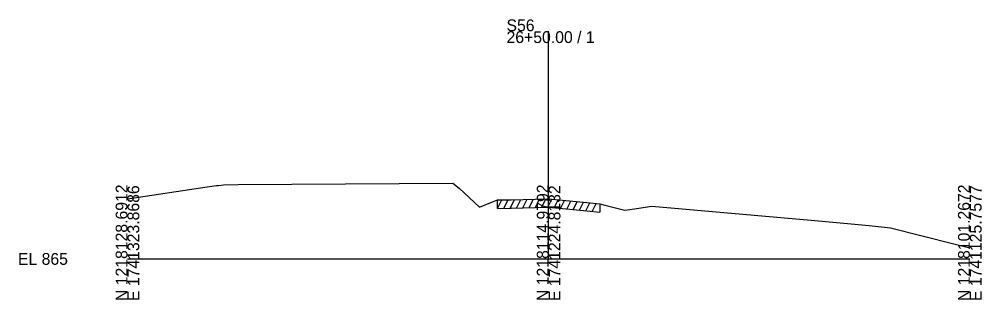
# Model space of a CAD drawing. Extents: x -26 to 1203, y -10 to 19541.
# Drawn here: x -25.7 to 202.8, y 1490.3 to 1556.9 of the extents above; entities that cross this region are included whole.
import ezdxf

# ---------------------------------------------------------------- set-up
doc = ezdxf.new("R2010")
doc.units = 0
for name, color, linetype in [('RD_GPK_XS_Cell', 7, 'Continuous'), ('RD_XS_ExGround', 7, 'Continuous'), ('RD_XS_ExPaveRet', 7, 'Continuous'), ('RD_XS_TX_Elev_EX', 7, 'Continuous')]:
    doc.layers.add(name, color=color, linetype=linetype)

msp = doc.modelspace()

# ---------------------------------------------------------------- linework, layer by layer
at = {"layer": 'RD_GPK_XS_Cell'}
for p, q in [((100, 1500), (100, 1554.08)), ((0, 1500), (100, 1500)), ((100, 1500), (200, 1500))]:
    msp.add_line(p, q, dxfattribs=at)
at = {"layer": 'RD_XS_ExGround'}
msp.add_lwpolyline([(0, 1514.29), (18.94, 1517.09), (21.17, 1517.41), (21.62, 1517.45), (22.84, 1517.63), (26.26, 1517.67), (77.27, 1518.03), (78.79, 1516.77), (83.55, 1512.26), (86.66, 1513.6), (87.85, 1514), (91.08, 1514.05), (99.65, 1514.31), (100, 1514.27), (109.1, 1513.39), (112.14, 1513.09), (113.35, 1512.78), (118.06, 1511.62), (119.86, 1511.84), (124.49, 1512.5), (163.23, 1509.13), (176.07, 1507.97), (181.16, 1507.35), (196.19, 1503.62), (200, 1502.67)], dxfattribs=at)
at = {"layer": 'RD_XS_ExPaveRet'}
for p, q in [((87.85, 1512), (88.86, 1514.01)), ((87.85, 1512), (87.85, 1514)), ((89.35, 1512.02), (90.36, 1514.04)), ((90.85, 1512.04), (91.86, 1514.07)), ((92.35, 1512.08), (93.37, 1514.12)), ((93.85, 1512.13), (94.87, 1514.16)), ((95.35, 1512.18), (96.37, 1514.21)), ((96.85, 1512.22), (97.87, 1514.25)), ((98.35, 1512.27), (99.37, 1514.3)), ((99.85, 1512.29), (100.8, 1514.19)), ((101.35, 1512.14), (102.3, 1514.05)), ((102.85, 1511.99), (103.8, 1513.9)), ((104.35, 1511.85), (105.3, 1513.76)), ((105.85, 1511.7), (106.8, 1513.61)), ((107.35, 1511.56), (108.3, 1513.46)), ((108.85, 1511.41), (109.8, 1513.32)), ((110.35, 1511.26), (111.3, 1513.17)), ((112.14, 1513.09), (112.14, 1511.09)), ((87.85, 1512), (91.08, 1512.05)), ((91.08, 1512.05), (99.65, 1512.31)), ((99.65, 1512.31), (100, 1512.27)), ((100, 1512.27), (109.1, 1511.39)), ((109.1, 1511.39), (112.14, 1511.09))]:
    msp.add_line(p, q, dxfattribs=at)

# ---------------------------------------------------------------- texts
at = {"layer": 'RD_GPK_XS_Cell'}
for s, p in [('S56', (90, 1554.08)), ('26+50.00 / 1', (90, 1551.28)), ('EL 865', (-26, 1498.6))]:
    msp.add_text(s, height=2.8, dxfattribs=at).set_placement(p)
for s, p in [('N 1218128.6912', (0, 1490)), ('N 1218114.9792', (100, 1490)), ('N 1218101.2672', (200, 1490)), ('E 1741323.8686', (2.8, 1490)), ('E 1741224.8132', (102.8, 1490)), ('E 1741125.7577', (202.8, 1490))]:
    msp.add_text(s, height=2.8, rotation=90, dxfattribs=at).set_placement(p)
at = {"layer": 'RD_XS_TX_Elev_EX'}
msp.add_text('872.14', height=0.1, rotation=90, dxfattribs=at).set_placement((100.1, 1514.27))

doc.saveas('drawing.dxf')
